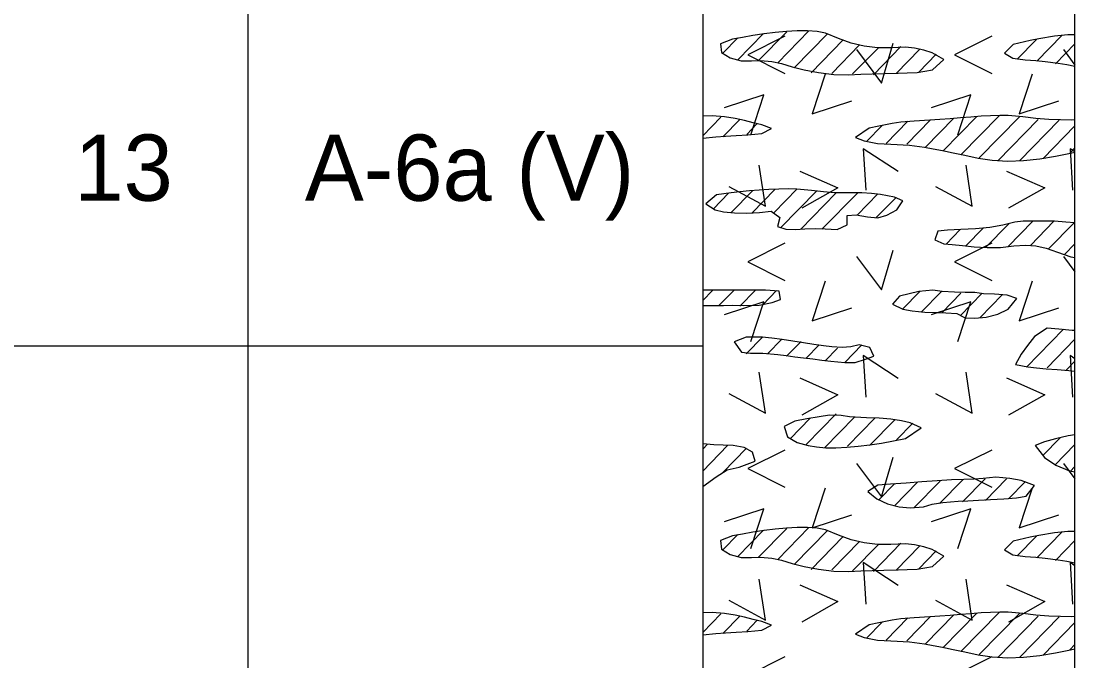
# Model space of a CAD drawing. Extents: x 0 to 0.83, y -0.65 to 1.27.
# Drawn here: x 0.7272 to 0.8333, y 0.5064 to 0.5708 of the extents above; entities that cross this region are included whole.
import ezdxf

# ---------------------------------------------------------------- set-up
doc = ezdxf.new("R2010")
doc.units = 0

msp = doc.modelspace()

# ---------------------------------------------------------------- linework, layer by layer
for points in [[(0, 0), (0.83333, 0), (0.83333, 1.275), (0, 1.275)], [(0, 0), (0.83333, 0), (0.83333, 1.275), (0, 1.275)], [(0, 0), (0.83333, 0), (0.83333, 1.275), (0, 1.275)], [(0, 0), (0.83333, 0), (0.83333, 1.275), (0, 1.275)], [(0, 0), (0.83333, 0), (0.83333, 1.275), (0, 1.275)], [(0.79885, 0.569), (0.79763, 0.56854), (0.79773, 0.56764), (0.79859, 0.56712), (0.7997, 0.56682), (0.80074, 0.56683), (0.80165, 0.56684), (0.80281, 0.56676), (0.80377, 0.56655), (0.80486, 0.5662), (0.80606, 0.56591), (0.80751, 0.56563), (0.80905, 0.56545), (0.81052, 0.56542), (0.81177, 0.56547), (0.81289, 0.56551), (0.81408, 0.56555), (0.81553, 0.56559), (0.81642, 0.56562), (0.81745, 0.56565), (0.81897, 0.56592), (0.82011, 0.56696), (0.81896, 0.56763), (0.8181, 0.56789), (0.81717, 0.56809), (0.81626, 0.56819), (0.81479, 0.56814), (0.81343, 0.56814), (0.8121, 0.56829), (0.8108, 0.56859), (0.80953, 0.56905), (0.8082, 0.5696), (0.80736, 0.56976), (0.8064, 0.56984), (0.80536, 0.56984), (0.80427, 0.56978), (0.80314, 0.56967), (0.80201, 0.56952), (0.8009, 0.56935), (0.79984, 0.56917)], [(0.83263, 0.56944), (0.83126, 0.5693), (0.82969, 0.56904), (0.82883, 0.56887), (0.82712, 0.56846), (0.82623, 0.56759), (0.82708, 0.56709), (0.82831, 0.56691), (0.82941, 0.56684), (0.83033, 0.56675), (0.83165, 0.56657), (0.83253, 0.56643), (0.83333, 0.56629), (0.83333, 0.56944)], [(0.79583, 0.55904), (0.79715, 0.55915), (0.79814, 0.55922), (0.79922, 0.5593), (0.80039, 0.55938), (0.80179, 0.55951), (0.80275, 0.56002), (0.80179, 0.56036), (0.80091, 0.56058), (0.80003, 0.5608), (0.79909, 0.561), (0.79803, 0.56117), (0.79677, 0.56127), (0.79583, 0.56124)], [(0.82816, 0.55679), (0.82978, 0.55696), (0.83137, 0.55721), (0.8329, 0.55752), (0.83333, 0.55763), (0.83333, 0.56087), (0.83295, 0.56084), (0.83188, 0.56086), (0.83071, 0.56091), (0.82938, 0.56101), (0.82807, 0.56118), (0.82662, 0.5613), (0.82576, 0.5613), (0.82484, 0.56128), (0.82387, 0.56123), (0.82286, 0.56116), (0.82182, 0.56108), (0.82077, 0.56099), (0.81973, 0.56091), (0.81872, 0.56084), (0.81715, 0.56074), (0.81579, 0.56065), (0.81491, 0.56051), (0.81357, 0.56024), (0.8126, 0.56003), (0.81121, 0.55911), (0.8121, 0.55875), (0.81345, 0.5585), (0.81479, 0.55841), (0.81668, 0.55831), (0.81818, 0.55811), (0.81905, 0.55796), (0.82, 0.55778), (0.82107, 0.55757), (0.82225, 0.55732), (0.82357, 0.55703), (0.82501, 0.5568), (0.82656, 0.55673)], [(0.79708, 0.55181), (0.79794, 0.55163), (0.79904, 0.55152), (0.80028, 0.55149), (0.80156, 0.55154), (0.80274, 0.55169), (0.80361, 0.55103), (0.80338, 0.55014), (0.80422, 0.54987), (0.80517, 0.54985), (0.80613, 0.5499), (0.8072, 0.54993), (0.80818, 0.5499), (0.80939, 0.54983), (0.81037, 0.55029), (0.81038, 0.55124), (0.8113, 0.5513), (0.81244, 0.55112), (0.81346, 0.55101), (0.81438, 0.55127), (0.81539, 0.55181), (0.81601, 0.55272), (0.81517, 0.55309), (0.81374, 0.55337), (0.81285, 0.55346), (0.81187, 0.55352), (0.81, 0.55352), (0.8091, 0.55354), (0.808, 0.55362), (0.80678, 0.55377), (0.8053, 0.5539), (0.80443, 0.55392), (0.80349, 0.5539), (0.80251, 0.55386), (0.80152, 0.5538), (0.80054, 0.55372), (0.79959, 0.55363), (0.7987, 0.55353), (0.79722, 0.55331), (0.79614, 0.55243)], [(0.83241, 0.55059), (0.83129, 0.55066), (0.83017, 0.55069), (0.8291, 0.55069), (0.82811, 0.55066), (0.82728, 0.55057), (0.82608, 0.55027), (0.82476, 0.55004), (0.8233, 0.5499), (0.82183, 0.54982), (0.82051, 0.54976), (0.81951, 0.54966), (0.81922, 0.5488), (0.82013, 0.54838), (0.82097, 0.54833), (0.822, 0.54823), (0.82318, 0.5481), (0.82448, 0.54801), (0.82584, 0.54804), (0.82719, 0.5482), (0.82836, 0.54827), (0.8294, 0.54819), (0.83043, 0.54795), (0.83156, 0.54756), (0.83291, 0.54707), (0.83333, 0.547), (0.83333, 0.55052)], [(0.79583, 0.54218), (0.79676, 0.54217), (0.79792, 0.54219), (0.79882, 0.54223), (0.79992, 0.54218), (0.80151, 0.54223), (0.80282, 0.54248), (0.80367, 0.5428), (0.80354, 0.54364), (0.80216, 0.54373), (0.79583, 0.54373)], [(0.81822, 0.54153), (0.81944, 0.54147), (0.82033, 0.54143), (0.82145, 0.54137), (0.82229, 0.54095), (0.82324, 0.54091), (0.82438, 0.54101), (0.82555, 0.5413), (0.82662, 0.54181), (0.82749, 0.5429), (0.82651, 0.54321), (0.82524, 0.54331), (0.82413, 0.54337), (0.82324, 0.54348), (0.82226, 0.5435), (0.82121, 0.54352), (0.81995, 0.54361), (0.81902, 0.54373), (0.81761, 0.54359), (0.81566, 0.54314), (0.81496, 0.54231), (0.81598, 0.54182), (0.81695, 0.54164)], [(0.83305, 0.53968), (0.83171, 0.53979), (0.83054, 0.53989), (0.82925, 0.53907), (0.82857, 0.53816), (0.82792, 0.53727), (0.82735, 0.53624), (0.82858, 0.53602), (0.82945, 0.53592), (0.83045, 0.53582), (0.83155, 0.53573), (0.83272, 0.53563), (0.83333, 0.53558), (0.83333, 0.53967)], [(0.80066, 0.53738), (0.80188, 0.53737), (0.80339, 0.53724), (0.80423, 0.53714), (0.8051, 0.53703), (0.806, 0.53692), (0.80692, 0.5368), (0.80784, 0.53668), (0.80875, 0.53657), (0.81014, 0.53643), (0.81119, 0.53644), (0.81222, 0.53678), (0.81308, 0.53707), (0.81267, 0.53797), (0.8116, 0.53822), (0.81075, 0.53802), (0.80989, 0.53794), (0.80885, 0.53802), (0.80799, 0.53813), (0.80703, 0.53827), (0.806, 0.53844), (0.80492, 0.5386), (0.80384, 0.53876), (0.8028, 0.53889), (0.80182, 0.53898), (0.8002, 0.53899), (0.79901, 0.53852), (0.79974, 0.53748)], [(0.81233, 0.53087), (0.81063, 0.53099), (0.80977, 0.53112), (0.8086, 0.53113), (0.80755, 0.53099), (0.80632, 0.53079), (0.80513, 0.53054), (0.80403, 0.53002), (0.80436, 0.52896), (0.80536, 0.52839), (0.80647, 0.5281), (0.8073, 0.52795), (0.80824, 0.52787), (0.80926, 0.52786), (0.81035, 0.52791), (0.81149, 0.52801), (0.81267, 0.52816), (0.81386, 0.52834), (0.81506, 0.52856), (0.81625, 0.52879), (0.81783, 0.52987), (0.81673, 0.53037), (0.81585, 0.53057), (0.8148, 0.53073), (0.81361, 0.53083)], [(0.83265, 0.52906), (0.83136, 0.52875), (0.83028, 0.52847), (0.82934, 0.52808), (0.83026, 0.52688), (0.83142, 0.52612), (0.83279, 0.52554), (0.83333, 0.52544), (0.83333, 0.52915)], [(0.79583, 0.52396), (0.79719, 0.52495), (0.79831, 0.52565), (0.79951, 0.52592), (0.80111, 0.52653), (0.80086, 0.52741), (0.80002, 0.52789), (0.79889, 0.52808), (0.79791, 0.52811), (0.79694, 0.52817), (0.79583, 0.52825)], [(0.82537, 0.5249), (0.82408, 0.52476), (0.82319, 0.5247), (0.82214, 0.52467), (0.82091, 0.52464), (0.81947, 0.52454), (0.81792, 0.52442), (0.81632, 0.5243), (0.81475, 0.52421), (0.81348, 0.52411), (0.81247, 0.52347), (0.81337, 0.52271), (0.81444, 0.52221), (0.81561, 0.52192), (0.81675, 0.52181), (0.81807, 0.52193), (0.81896, 0.5222), (0.82003, 0.52234), (0.82157, 0.52247), (0.82253, 0.52252), (0.82362, 0.52258), (0.82483, 0.52264), (0.82618, 0.52271), (0.82745, 0.52282), (0.82842, 0.52299), (0.82927, 0.52405), (0.82791, 0.52457), (0.82679, 0.52477)], [(0.79885, 0.519), (0.79763, 0.51854), (0.79773, 0.51764), (0.79859, 0.51712), (0.7997, 0.51682), (0.80074, 0.51683), (0.80165, 0.51684), (0.80281, 0.51676), (0.80377, 0.51655), (0.80486, 0.5162), (0.80606, 0.51591), (0.80751, 0.51563), (0.80905, 0.51545), (0.81052, 0.51542), (0.81177, 0.51547), (0.81289, 0.51551), (0.81408, 0.51555), (0.81553, 0.51559), (0.81642, 0.51562), (0.81745, 0.51565), (0.81897, 0.51592), (0.82011, 0.51696), (0.81896, 0.51763), (0.8181, 0.51789), (0.81717, 0.51809), (0.81626, 0.51819), (0.81479, 0.51814), (0.81343, 0.51814), (0.8121, 0.51829), (0.8108, 0.51859), (0.80953, 0.51905), (0.8082, 0.5196), (0.80736, 0.51976), (0.8064, 0.51984), (0.80536, 0.51984), (0.80427, 0.51978), (0.80314, 0.51967), (0.80201, 0.51952), (0.8009, 0.51935), (0.79984, 0.51917)], [(0.83263, 0.51944), (0.83126, 0.5193), (0.82969, 0.51904), (0.82883, 0.51887), (0.82712, 0.51846), (0.82623, 0.51759), (0.82708, 0.5171), (0.82831, 0.51691), (0.82941, 0.51684), (0.83033, 0.51675), (0.83165, 0.51657), (0.83253, 0.51643), (0.83333, 0.51629), (0.83333, 0.51944)], [(0.79583, 0.50904), (0.79715, 0.50915), (0.79814, 0.50922), (0.79922, 0.5093), (0.80039, 0.50938), (0.80179, 0.50951), (0.80275, 0.51002), (0.80179, 0.51036), (0.80091, 0.51058), (0.80003, 0.5108), (0.79909, 0.511), (0.79803, 0.51117), (0.79677, 0.51127), (0.79583, 0.51125)], [(0.82816, 0.50679), (0.82978, 0.50696), (0.83137, 0.50721), (0.8329, 0.50752), (0.83333, 0.50763), (0.83333, 0.51087), (0.83295, 0.51084), (0.83188, 0.51086), (0.83071, 0.51091), (0.82938, 0.51101), (0.82807, 0.51118), (0.82662, 0.5113), (0.82576, 0.5113), (0.82484, 0.51128), (0.82387, 0.51123), (0.82286, 0.51116), (0.82182, 0.51108), (0.82077, 0.51099), (0.81973, 0.51091), (0.81872, 0.51084), (0.81715, 0.51074), (0.81579, 0.51065), (0.81491, 0.51052), (0.81357, 0.51024), (0.8126, 0.51003), (0.81121, 0.50911), (0.8121, 0.50875), (0.81345, 0.5085), (0.81479, 0.50841), (0.81668, 0.50831), (0.81818, 0.50811), (0.81905, 0.50796), (0.82, 0.50778), (0.82107, 0.50757), (0.82225, 0.50732), (0.82357, 0.50703), (0.82501, 0.5068), (0.82656, 0.50673)]]:
    msp.add_lwpolyline(points, close=True)
for points in [[(0.75, 1.22083), (0.75, -0.64575)], [(0.75, 1.22083), (0.75, -0.64575)], [(0.79583, 1.22083), (0.79583, -0.64575)], [(0.83333, -0.64575), (0.83333, 1.13365)], [(0.79938, 0.56913), (0.79786, 0.56758)], [(0.79933, 0.56687), (0.80195, 0.56956)], [(0.80412, 0.5693), (0.80038, 0.56742), (0.80412, 0.56555)], [(0.80142, 0.5668), (0.8043, 0.56975)], [(0.80653, 0.56983), (0.8034, 0.56661)], [(0.80506, 0.5661), (0.8084, 0.56952)], [(0.82496, 0.5693), (0.82121, 0.56742), (0.82496, 0.56555)], [(0.83203, 0.56939), (0.82949, 0.56679)], [(0.80997, 0.56893), (0.80675, 0.56562)], [(0.81164, 0.56842), (0.80884, 0.56555)], [(0.81353, 0.56814), (0.81094, 0.56549)], [(0.81134, 0.56796), (0.81384, 0.56458), (0.81503, 0.56858)], [(0.81303, 0.56542), (0.81579, 0.56825)], [(0.82751, 0.56698), (0.82945, 0.56896)], [(0.83138, 0.56652), (0.83333, 0.56852)], [(0.81534, 0.56558), (0.81768, 0.56797)], [(0.8176, 0.56568), (0.81934, 0.56747)], [(0.83217, 0.56796), (0.83333, 0.56639)], [(0.83333, 0.5663), (0.83333, 0.5663)], [(0.80818, 0.56547), (0.80687, 0.56147), (0.81087, 0.56278)], [(0.82901, 0.56547), (0.8277, 0.56147), (0.8317, 0.56278)], [(0.80069, 0.55938), (0.802, 0.56338), (0.798, 0.56207)], [(0.82152, 0.55938), (0.82284, 0.56338), (0.81884, 0.56207)], [(0.79765, 0.56115), (0.79583, 0.55928)], [(0.7996, 0.56094), (0.79786, 0.55915)], [(0.8143, 0.55848), (0.8165, 0.56073)], [(0.8164, 0.55841), (0.81879, 0.56086)], [(0.81829, 0.55813), (0.82114, 0.56105)], [(0.82004, 0.55771), (0.82346, 0.56122)], [(0.82569, 0.56129), (0.82184, 0.55735)], [(0.82775, 0.56119), (0.8237, 0.55704)], [(0.82964, 0.56092), (0.82557, 0.55674)], [(0.83173, 0.56085), (0.82774, 0.55676)], [(0.8013, 0.56046), (0.80027, 0.55941)], [(0.81392, 0.5603), (0.81235, 0.55869)], [(0.83333, 0.56027), (0.83012, 0.55698)], [(0.81551, 0.55566), (0.81201, 0.55797), (0.81226, 0.55378)], [(0.83281, 0.55752), (0.83333, 0.55806)], [(0.83333, 0.55765), (0.83284, 0.55797), (0.83309, 0.55378)], [(0.79847, 0.55418), (0.80215, 0.55218), (0.80153, 0.5563)], [(0.80562, 0.55572), (0.80946, 0.55404), (0.80581, 0.55198)], [(0.8193, 0.55418), (0.82299, 0.55218), (0.82236, 0.5563)], [(0.82645, 0.55572), (0.83029, 0.55404), (0.82664, 0.55198)], [(0.79844, 0.55349), (0.79691, 0.55192)], [(0.79871, 0.55155), (0.80085, 0.55374)], [(0.80083, 0.55151), (0.80311, 0.55385)], [(0.80534, 0.55392), (0.80299, 0.55151)], [(0.80367, 0.55), (0.80732, 0.55374)], [(0.80571, 0.54988), (0.80924, 0.55349)], [(0.81142, 0.55351), (0.80785, 0.54986)], [(0.81141, 0.55129), (0.81348, 0.55341)], [(0.81528, 0.55304), (0.81331, 0.55103)], [(0.82233, 0.54819), (0.82408, 0.54998)], [(0.82433, 0.54802), (0.82666, 0.55041)], [(0.82909, 0.55069), (0.82656, 0.5481)], [(0.82885, 0.54823), (0.83122, 0.55066)], [(0.83325, 0.55052), (0.83065, 0.54786)], [(0.82035, 0.54837), (0.82176, 0.54982)], [(0.80412, 0.54846), (0.80038, 0.54659), (0.80412, 0.54471)], [(0.82496, 0.54846), (0.82121, 0.54659), (0.82496, 0.54471)], [(0.83333, 0.5484), (0.83227, 0.54731)], [(0.81134, 0.54712), (0.81384, 0.54375), (0.81503, 0.54775)], [(0.83217, 0.54712), (0.83333, 0.54556)], [(0.79583, 0.5427), (0.79681, 0.5437)], [(0.79898, 0.54371), (0.79747, 0.54217)], [(0.80116, 0.54373), (0.79959, 0.54213)], [(0.80328, 0.54369), (0.80188, 0.54226)], [(0.80818, 0.54463), (0.80687, 0.54063), (0.81087, 0.54194)], [(0.8177, 0.54359), (0.81596, 0.54181)], [(0.81988, 0.54361), (0.81785, 0.54153)], [(0.82901, 0.54463), (0.8277, 0.54063), (0.8317, 0.54194)], [(0.80069, 0.53855), (0.802, 0.54255), (0.798, 0.54124)], [(0.82152, 0.53855), (0.82284, 0.54255), (0.81884, 0.54124)], [(0.82185, 0.54342), (0.81997, 0.54149)], [(0.824, 0.54341), (0.82178, 0.54113)], [(0.82601, 0.54325), (0.82378, 0.54097)], [(0.83217, 0.5398), (0.82844, 0.53599)], [(0.80188, 0.53903), (0.8002, 0.53731)], [(0.8038, 0.53879), (0.80237, 0.53732)], [(0.80575, 0.53857), (0.80429, 0.53708)], [(0.83333, 0.53879), (0.83052, 0.53591)], [(0.725, 0.53812), (0.75, 0.53812)], [(0.75, 0.53812), (0.79583, 0.53812)], [(0.80758, 0.53824), (0.80627, 0.53689)], [(0.80941, 0.5379), (0.80816, 0.53662)], [(0.81188, 0.53821), (0.81016, 0.53646)], [(0.81551, 0.53483), (0.81201, 0.53714), (0.81226, 0.53295)], [(0.83333, 0.53657), (0.83245, 0.53567)], [(0.83333, 0.53682), (0.83284, 0.53714), (0.83309, 0.53295)], [(0.79847, 0.53334), (0.80215, 0.53134), (0.80153, 0.53547)], [(0.8193, 0.53334), (0.82299, 0.53134), (0.82236, 0.53547)], [(0.80562, 0.53489), (0.80946, 0.5332), (0.80581, 0.53114)], [(0.82645, 0.53489), (0.83029, 0.5332), (0.82664, 0.53114)], [(0.80626, 0.52819), (0.80928, 0.53128)], [(0.80809, 0.52785), (0.81111, 0.53095)], [(0.81041, 0.52802), (0.81318, 0.53085)], [(0.80465, 0.52875), (0.80667, 0.53083)], [(0.81264, 0.52809), (0.81518, 0.53069)], [(0.81536, 0.52867), (0.81699, 0.53033)], [(0.8301, 0.52709), (0.83184, 0.52887)], [(0.7963, 0.52821), (0.79583, 0.52772)], [(0.79834, 0.52808), (0.79583, 0.52551)], [(0.79786, 0.52538), (0.80023, 0.52781)], [(0.83131, 0.52612), (0.83333, 0.52819)], [(0.80412, 0.52763), (0.80038, 0.52576), (0.80412, 0.52388)], [(0.81134, 0.52629), (0.81384, 0.52291), (0.81503, 0.52691)], [(0.82496, 0.52763), (0.82121, 0.52576), (0.82496, 0.52388)], [(0.83217, 0.52629), (0.83333, 0.52473)], [(0.83285, 0.52549), (0.83333, 0.52598)], [(0.81709, 0.5218), (0.81974, 0.52451)], [(0.8197, 0.52225), (0.82203, 0.52465)], [(0.82202, 0.52241), (0.8243, 0.52475)], [(0.82431, 0.52255), (0.82644, 0.52474)], [(0.80818, 0.5238), (0.80687, 0.5198), (0.81087, 0.52111)], [(0.81519, 0.52428), (0.81354, 0.52258)], [(0.81514, 0.52201), (0.81748, 0.52441)], [(0.82663, 0.52271), (0.82834, 0.52447)], [(0.82901, 0.5238), (0.8277, 0.5198), (0.8317, 0.52111)], [(0.80069, 0.51772), (0.802, 0.52172), (0.798, 0.52041)], [(0.82152, 0.51772), (0.82284, 0.52172), (0.81884, 0.52041)], [(0.79933, 0.51687), (0.80195, 0.51956)], [(0.80142, 0.5168), (0.8043, 0.51975)], [(0.80653, 0.51983), (0.8034, 0.51661)], [(0.80506, 0.5161), (0.8084, 0.51952)], [(0.83203, 0.51939), (0.82949, 0.51679)], [(0.79938, 0.51913), (0.79786, 0.51758)], [(0.80997, 0.51893), (0.80675, 0.51562)], [(0.81164, 0.51842), (0.80884, 0.51556)], [(0.81353, 0.51814), (0.81094, 0.51549)], [(0.81303, 0.51542), (0.81579, 0.51825)], [(0.82751, 0.51698), (0.82945, 0.51896)], [(0.83138, 0.51652), (0.83333, 0.51852)], [(0.81534, 0.51558), (0.81768, 0.51797)], [(0.8176, 0.51568), (0.81934, 0.51747)], [(0.81551, 0.51399), (0.81201, 0.5163), (0.81226, 0.51212)], [(0.83333, 0.51598), (0.83284, 0.5163), (0.83309, 0.51212)], [(0.83333, 0.5163), (0.83333, 0.5163)], [(0.79847, 0.51251), (0.80215, 0.51051), (0.80153, 0.51463)], [(0.80562, 0.51406), (0.80946, 0.51237), (0.80581, 0.51031)], [(0.8193, 0.51251), (0.82299, 0.51051), (0.82236, 0.51463)], [(0.82645, 0.51406), (0.83029, 0.51237), (0.82664, 0.51031)], [(0.79765, 0.51115), (0.79583, 0.50928)], [(0.7996, 0.51094), (0.79786, 0.50915)], [(0.8143, 0.50848), (0.8165, 0.51073)], [(0.8164, 0.50841), (0.81879, 0.51086)], [(0.81829, 0.50813), (0.82114, 0.51105)], [(0.82004, 0.50771), (0.82346, 0.51122)], [(0.82569, 0.51129), (0.82184, 0.50735)], [(0.82775, 0.51119), (0.8237, 0.50704)], [(0.82964, 0.51092), (0.82557, 0.50674)], [(0.83173, 0.51085), (0.82774, 0.50676)], [(0.8013, 0.51046), (0.80027, 0.50941)], [(0.81392, 0.5103), (0.81235, 0.50869)], [(0.83333, 0.51027), (0.83012, 0.50698)], [(0.83281, 0.50752), (0.83333, 0.50806)], [(0.80412, 0.5068), (0.80038, 0.50492), (0.80412, 0.50305)], [(0.82496, 0.5068), (0.82121, 0.50492), (0.82496, 0.50305)]]:
    msp.add_lwpolyline(points)

# ---------------------------------------------------------------- texts
for s, p in [('A-6a (V)', (0.75575, 0.55273)), ('13', (0.73253, 0.55273))]:
    msp.add_text(s, height=0.006667).set_placement(p)

doc.saveas('drawing.dxf')
